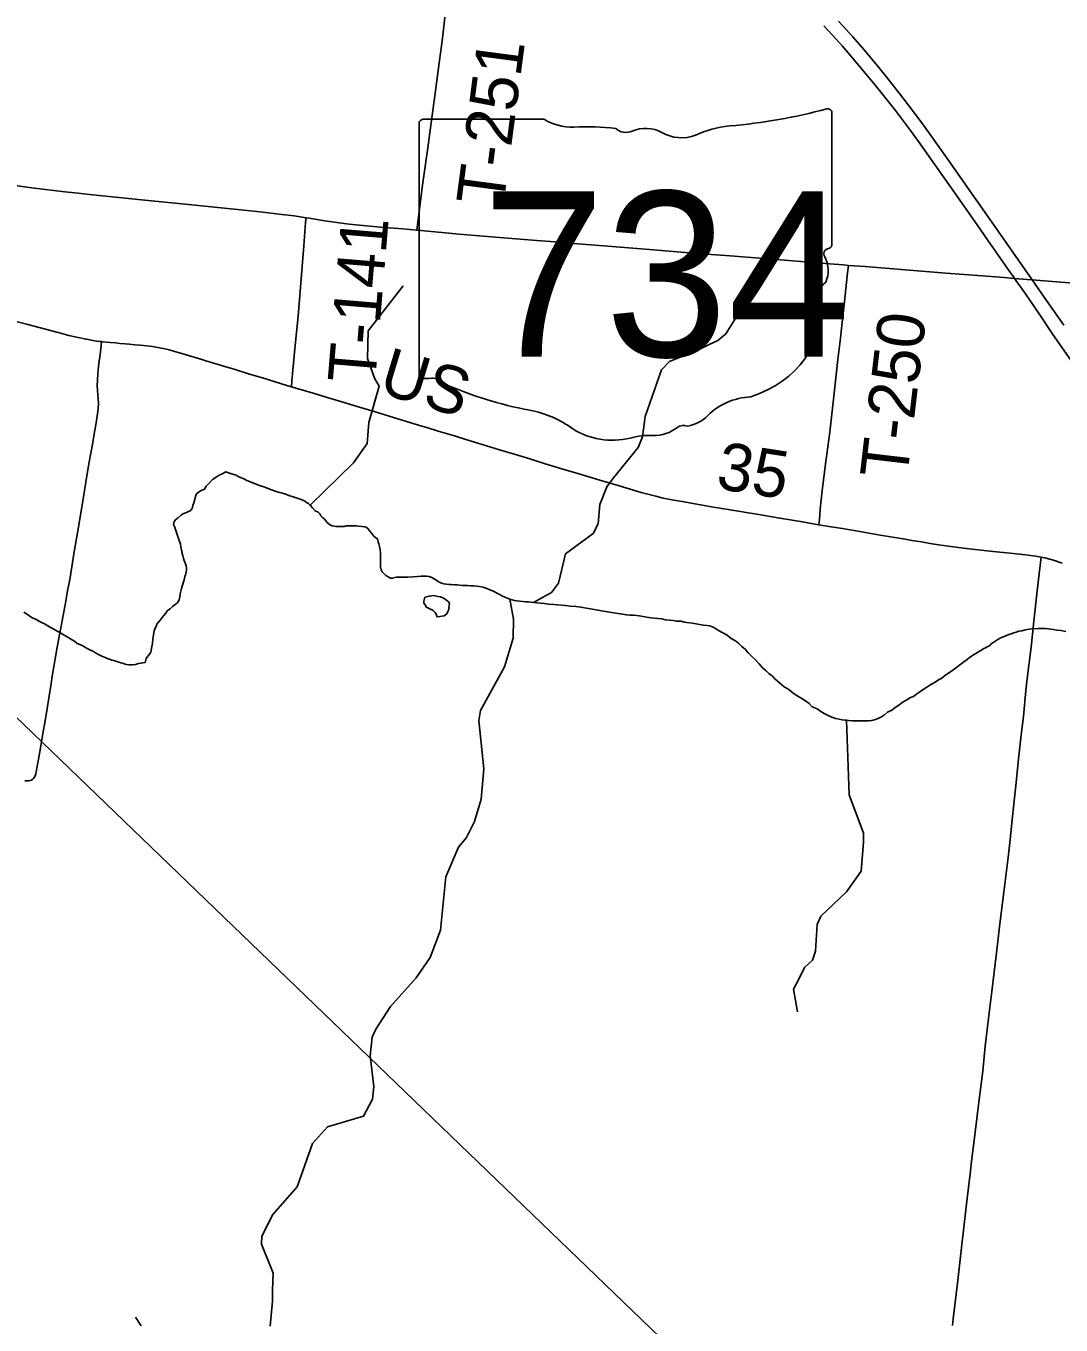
# Model space of a CAD drawing. Extents: x -49 to -8.2, y 9.4 to 23.5.
# Drawn here: x -43.786 to -43.166, y 18.097 to 18.874 of the extents above; entities that cross this region are included whole.
import ezdxf

# ---------------------------------------------------------------- set-up
doc = ezdxf.new("R2010")
doc.units = 0
for name, color, linetype in [('GM_X_County_Road', 7, 'Continuous'), ('GM_X_County_Road_Text', 7, 'Continuous'), ('GM_X_Minor_Lake', 7, 'Continuous'), ('GM_X_Minor_River', 7, 'Continuous'), ('GM_X_State_Route', 7, 'Continuous'), ('GM_X_State_Shield', 7, 'Continuous'), ('GM_X_Township_Road', 7, 'Continuous'), ('GM_X_Township_Road_Text', 7, 'Continuous'), ('GM_X_US_Route', 7, 'Continuous'), ('SC_Scratch1', 7, 'Continuous')]:
    doc.layers.add(name, color=color, linetype=linetype)

msp = doc.modelspace()

# ---------------------------------------------------------------- linework, layer by layer
at = {"layer": 'GM_X_County_Road'}
for points in [[(-43.7985, 18.69919), (-43.78469, 18.69553), (-43.76728, 18.69092), (-43.76429, 18.69012), (-43.76008, 18.68906), (-43.75554, 18.688), (-43.75341, 18.68754), (-43.74976, 18.68678), (-43.74731, 18.68634), (-43.74568, 18.68603), (-43.74346, 18.68567), (-43.74161, 18.68541), (-43.74054, 18.68529)], [(-43.74054, 18.68529), (-43.74001, 18.68523), (-43.73776, 18.68507), (-43.73529, 18.68481), (-43.7322, 18.68452), (-43.72942, 18.68426), (-43.72632, 18.68399), (-43.72385, 18.68378), (-43.72045, 18.68348), (-43.71736, 18.68319), (-43.71336, 18.68277), (-43.70998, 18.68232), (-43.70694, 18.68184), (-43.7036, 18.68118), (-43.69998, 18.68036), (-43.69729, 18.67965), (-43.6952, 18.67908), (-43.69044, 18.67768), (-43.68093, 18.67482), (-43.67797, 18.6739), (-43.66668, 18.67045), (-43.66045, 18.66855), (-43.65184, 18.6659), (-43.64411, 18.66354), (-43.6364, 18.66116), (-43.62688, 18.65828), (-43.62675, 18.65825)], [(-43.62675, 18.65825), (-43.62361, 18.65732), (-43.61914, 18.656), (-43.6117, 18.6538), (-43.60545, 18.65194), (-43.59653, 18.64927), (-43.58731, 18.64649), (-43.57721, 18.64341), (-43.56831, 18.64065), (-43.55789, 18.63754), (-43.54867, 18.63476), (-43.5457, 18.63385), (-43.53888, 18.63178), (-43.52908, 18.62885), (-43.52225, 18.6268), (-43.51246, 18.6238), (-43.5021, 18.62055), (-43.49261, 18.61768), (-43.484, 18.61505), (-43.47478, 18.61224), (-43.46079, 18.60805), (-43.45722, 18.60699), (-43.4486, 18.60439), (-43.43998, 18.60175), (-43.43106, 18.59908), (-43.41734, 18.59507), (-43.40863, 18.59274), (-43.40408, 18.59168), (-43.39768, 18.59037), (-43.39156, 18.58932), (-43.3851, 18.58816), (-43.37522, 18.58647), (-43.3578, 18.58357), (-43.35443, 18.58301), (-43.34799, 18.58196), (-43.3342, 18.57967), (-43.32073, 18.57739), (-43.3143, 18.57629), (-43.31085, 18.5757)], [(-43.31085, 18.5757), (-43.30358, 18.57446), (-43.29685, 18.57334), (-43.28766, 18.57179), (-43.27421, 18.56951), (-43.25921, 18.56695), (-43.25522, 18.56631), (-43.24939, 18.56537), (-43.24541, 18.56472), (-43.23927, 18.56374), (-43.23035, 18.56243), (-43.22264, 18.56147), (-43.20657, 18.55976), (-43.19636, 18.55873), (-43.18711, 18.55774), (-43.18098, 18.55686), (-43.17781, 18.55625)], [(-43.23096, 18.09637), (-43.23046, 18.10038), (-43.22773, 18.1232), (-43.22525, 18.14481), (-43.22442, 18.15159), (-43.22222, 18.17073), (-43.22038, 18.1871), (-43.2193, 18.19635), (-43.21859, 18.20221), (-43.21512, 18.22997), (-43.21278, 18.24853), (-43.21127, 18.26355), (-43.21002, 18.27503), (-43.2086, 18.28675), (-43.20741, 18.29631), (-43.20457, 18.31944), (-43.2025, 18.33671), (-43.20007, 18.35582), (-43.19763, 18.37649), (-43.19618, 18.38914), (-43.19533, 18.39717), (-43.19392, 18.41045), (-43.19319, 18.41756), (-43.19244, 18.42529), (-43.19135, 18.43548), (-43.1897, 18.44999), (-43.18846, 18.46079), (-43.18688, 18.47655), (-43.18608, 18.48366), (-43.18386, 18.50248), (-43.18211, 18.51791), (-43.18016, 18.53614), (-43.17897, 18.54633), (-43.17781, 18.55625)], [(-43.17781, 18.55625), (-43.17552, 18.55581), (-43.17045, 18.55447), (-43.16517, 18.55269)]]:
    msp.add_lwpolyline(points, dxfattribs=at)
at = {"layer": 'GM_X_Minor_Lake'}
msp.add_lwpolyline([(-43.54658, 18.53224), (-43.5443, 18.53297), (-43.54259, 18.53314), (-43.54145, 18.53332), (-43.53918, 18.53273), (-43.53748, 18.53252), (-43.53615, 18.53193), (-43.53521, 18.53154), (-43.5337, 18.53038), (-43.53276, 18.52961), (-43.53202, 18.52847), (-43.53242, 18.52619), (-43.53244, 18.52486), (-43.53302, 18.52373), (-43.5336, 18.5224), (-43.53532, 18.52109), (-43.53798, 18.52074), (-43.5395, 18.52057), (-43.54005, 18.5221), (-43.54061, 18.52305), (-43.54193, 18.5244), (-43.54343, 18.52517), (-43.54476, 18.52576), (-43.54589, 18.52634), (-43.54663, 18.52768), (-43.54738, 18.52864), (-43.54737, 18.52997), (-43.54677, 18.53224), (-43.54658, 18.53224)], dxfattribs=at)
at = {"layer": 'GM_X_Minor_River'}
for points in [[(-43.48174, 18.52904), (-43.47096, 18.53518), (-43.46688, 18.5408), (-43.46259, 18.55819), (-43.44607, 18.57042), (-43.44313, 18.57626), (-43.44216, 18.58782), (-43.43781, 18.59838), (-43.43392, 18.60381), (-43.4192, 18.62197), (-43.41643, 18.62837), (-43.41489, 18.6405), (-43.40511, 18.66842), (-43.40028, 18.67346), (-43.38215, 18.68073), (-43.37698, 18.68348), (-43.37144, 18.68604), (-43.36664, 18.68994), (-43.35571, 18.70759), (-43.35225, 18.7212)], [(-43.61544, 18.58735), (-43.58952, 18.61273), (-43.58135, 18.62435), (-43.58037, 18.63686), (-43.5743, 18.65859), (-43.57706, 18.66339), (-43.58121, 18.67524), (-43.58072, 18.69175), (-43.55978, 18.71872)], [(-43.73253, 18.49424), (-43.73121, 18.49385), (-43.73007, 18.49346), (-43.72894, 18.49306), (-43.72799, 18.49286), (-43.72629, 18.49227), (-43.72535, 18.49207), (-43.72421, 18.49187), (-43.72307, 18.49186), (-43.72193, 18.49185), (-43.72022, 18.49202), (-43.71832, 18.49256), (-43.7168, 18.49274), (-43.71585, 18.49292), (-43.71433, 18.49328), (-43.71374, 18.49555), (-43.71104, 18.49932), (-43.71084, 18.50065), (-43.71043, 18.50273), (-43.71003, 18.50463), (-43.70982, 18.50729), (-43.70941, 18.50975), (-43.70921, 18.51108), (-43.70901, 18.51222), (-43.70861, 18.51335), (-43.70784, 18.51486), (-43.70726, 18.51619), (-43.7063, 18.51732), (-43.70514, 18.51882), (-43.70418, 18.52014), (-43.70322, 18.52127), (-43.70206, 18.52278), (-43.70091, 18.52429), (-43.69938, 18.52541), (-43.69804, 18.52672), (-43.69632, 18.52784), (-43.69517, 18.52878), (-43.69401, 18.53067), (-43.69361, 18.53256), (-43.69341, 18.53427), (-43.69301, 18.53598), (-43.69261, 18.53749), (-43.69222, 18.53901), (-43.69182, 18.54014), (-43.69143, 18.54147), (-43.69104, 18.54279), (-43.69064, 18.54469), (-43.69025, 18.54563), (-43.69005, 18.54658), (-43.68985, 18.54753), (-43.68965, 18.54848), (-43.68964, 18.54981), (-43.68981, 18.55114), (-43.69036, 18.55285), (-43.69092, 18.55419), (-43.69147, 18.55552), (-43.69183, 18.55724), (-43.6922, 18.55819), (-43.69219, 18.55914), (-43.69256, 18.56048), (-43.69292, 18.56219), (-43.69328, 18.56428), (-43.69401, 18.56619), (-43.69677, 18.57458), (-43.69733, 18.57592), (-43.69693, 18.57762), (-43.69578, 18.57894), (-43.69463, 18.57988), (-43.69271, 18.58138), (-43.69176, 18.58213), (-43.69061, 18.58268), (-43.68928, 18.58324), (-43.68833, 18.58361), (-43.68737, 18.58398), (-43.68622, 18.58548), (-43.68582, 18.58719), (-43.68524, 18.58889), (-43.68484, 18.59022), (-43.68445, 18.59154), (-43.68425, 18.59268), (-43.68366, 18.59419), (-43.68118, 18.59607), (-43.67889, 18.59699), (-43.67773, 18.59869), (-43.67601, 18.60057), (-43.67408, 18.60282), (-43.67179, 18.60413), (-43.67007, 18.60544), (-43.66817, 18.60618), (-43.66607, 18.60729), (-43.66323, 18.60631), (-43.66134, 18.60572), (-43.65983, 18.60532), (-43.6587, 18.60455), (-43.65719, 18.60397), (-43.6553, 18.60318), (-43.65341, 18.60221), (-43.65096, 18.60123), (-43.6485, 18.60026), (-43.64586, 18.59909), (-43.64264, 18.5981)], [(-43.64264, 18.5981), (-43.63924, 18.59673), (-43.63527, 18.59536), (-43.63073, 18.59417), (-43.62828, 18.59319), (-43.62563, 18.5924), (-43.62336, 18.59162), (-43.62147, 18.59102), (-43.61996, 18.59044), (-43.61864, 18.58985), (-43.6177, 18.58908), (-43.61657, 18.58831), (-43.61544, 18.58735), (-43.61413, 18.58581), (-43.61263, 18.58409), (-43.61074, 18.58312), (-43.6098, 18.58215), (-43.60905, 18.58101), (-43.60812, 18.58005), (-43.60699, 18.57908), (-43.60624, 18.57812), (-43.60549, 18.57717), (-43.60399, 18.57582), (-43.60229, 18.57504), (-43.60001, 18.57463), (-43.59812, 18.57461), (-43.59641, 18.57459), (-43.59527, 18.57458), (-43.59394, 18.57495), (-43.5928, 18.57512), (-43.58806, 18.57507), (-43.58635, 18.57486), (-43.58465, 18.57465), (-43.58294, 18.57444), (-43.582, 18.57424), (-43.58087, 18.57328), (-43.57993, 18.57213), (-43.57862, 18.5704), (-43.57731, 18.56887), (-43.57618, 18.56791), (-43.57524, 18.56733), (-43.57488, 18.56542), (-43.57432, 18.56428), (-43.57396, 18.56256), (-43.57378, 18.56161), (-43.5736, 18.56066), (-43.57343, 18.55876), (-43.57345, 18.55705), (-43.57347, 18.55534), (-43.57349, 18.55325), (-43.57332, 18.55154), (-43.57333, 18.55021), (-43.57297, 18.54868), (-43.57241, 18.54754), (-43.57129, 18.5462), (-43.57016, 18.54523), (-43.56884, 18.54446), (-43.56733, 18.54368), (-43.56638, 18.54367), (-43.5641, 18.54422), (-43.56107, 18.54437), (-43.55708, 18.54433), (-43.55404, 18.54448), (-43.5512, 18.54464), (-43.54911, 18.54481), (-43.5474, 18.54498), (-43.54588, 18.54496), (-43.54418, 18.54475), (-43.54266, 18.54416), (-43.53965, 18.54223), (-43.53871, 18.54146), (-43.53776, 18.54107), (-43.53682, 18.54068), (-43.5355, 18.54028), (-43.53398, 18.54008), (-43.53246, 18.53987), (-43.53114, 18.53986), (-43.52905, 18.53964), (-43.52753, 18.53962), (-43.52602, 18.53942), (-43.5245, 18.5394), (-43.52279, 18.53938), (-43.52128, 18.53936), (-43.51957, 18.53916), (-43.51767, 18.53913), (-43.51578, 18.53892), (-43.51426, 18.53872), (-43.51294, 18.53851), (-43.51199, 18.53831), (-43.51086, 18.53792), (-43.50972, 18.53752), (-43.5084, 18.53694), (-43.50689, 18.53635), (-43.50576, 18.53596), (-43.50481, 18.53538), (-43.50387, 18.53499), (-43.50293, 18.53441), (-43.50199, 18.53383), (-43.50067, 18.53305), (-43.49897, 18.53227), (-43.49594, 18.5311)], [(-43.49594, 18.5311), (-43.49379, 18.51907), (-43.49399, 18.50787), (-43.49922, 18.49069), (-43.51352, 18.46455), (-43.51458, 18.4585), (-43.51149, 18.42957), (-43.51314, 18.41138), (-43.51717, 18.39797), (-43.52189, 18.38837), (-43.52673, 18.38257), (-43.53424, 18.36486), (-43.53746, 18.33302), (-43.54363, 18.31661), (-43.55199, 18.30442), (-43.56746, 18.28723), (-43.57623, 18.27372), (-43.5784, 18.26882), (-43.57954, 18.25783), (-43.5774, 18.23937), (-43.57811, 18.23179), (-43.58359, 18.22163), (-43.60512, 18.21519), (-43.6142, 18.20529), (-43.62338, 18.17925), (-43.63789, 18.16281), (-43.64456, 18.14983), (-43.64464, 18.14508), (-43.63775, 18.12768), (-43.63812, 18.11743), (-43.63805, 18.11078), (-43.63946, 18.09581)], [(-43.49594, 18.5311), (-43.49311, 18.53031), (-43.49026, 18.5299), (-43.48818, 18.52968), (-43.48647, 18.52947), (-43.48477, 18.52945), (-43.48325, 18.52925), (-43.48174, 18.52904), (-43.47984, 18.52902), (-43.47775, 18.52881), (-43.47529, 18.52859), (-43.47283, 18.52818), (-43.4696, 18.52795), (-43.46733, 18.52774), (-43.46506, 18.52752), (-43.46259, 18.52731), (-43.45956, 18.52689), (-43.45653, 18.52667), (-43.4535, 18.52625), (-43.44554, 18.52502), (-43.44327, 18.52462), (-43.43986, 18.52401), (-43.43399, 18.52299), (-43.42963, 18.52238), (-43.42604, 18.52176), (-43.42414, 18.52155), (-43.42167, 18.52153), (-43.41845, 18.52111), (-43.41505, 18.5205), (-43.41145, 18.51989), (-43.40728, 18.51965), (-43.405, 18.51944), (-43.40273, 18.51884), (-43.40027, 18.51863), (-43.39799, 18.51841), (-43.39629, 18.51801), (-43.39458, 18.51799), (-43.39344, 18.51798), (-43.39155, 18.51739), (-43.39004, 18.51718), (-43.38663, 18.51676), (-43.38341, 18.51616), (-43.38019, 18.51555), (-43.37772, 18.51533), (-43.37621, 18.51513), (-43.37526, 18.51473), (-43.37413, 18.51434), (-43.37281, 18.51357), (-43.37092, 18.51241), (-43.36847, 18.51105), (-43.36583, 18.5095), (-43.36339, 18.50757), (-43.36075, 18.50621), (-43.35887, 18.50467), (-43.35699, 18.50275), (-43.35492, 18.50102), (-43.35323, 18.4991), (-43.35117, 18.49698), (-43.34891, 18.49487), (-43.34666, 18.49238), (-43.3446, 18.49007), (-43.34253, 18.48815), (-43.34084, 18.48661), (-43.33877, 18.48507), (-43.33727, 18.48353), (-43.33163, 18.47872), (-43.32899, 18.47698), (-43.32636, 18.47486), (-43.32353, 18.47312), (-43.32108, 18.47176), (-43.31882, 18.47022), (-43.31675, 18.46867), (-43.31487, 18.46675), (-43.31185, 18.46539), (-43.30978, 18.46384), (-43.30771, 18.46268), (-43.30544, 18.46151), (-43.30318, 18.46054), (-43.30091, 18.45975), (-43.29882, 18.45935), (-43.29693, 18.45895), (-43.29542, 18.45874), (-43.29428, 18.45873), (-43.29314, 18.45853), (-43.29106, 18.45831), (-43.28954, 18.4583), (-43.28802, 18.45828), (-43.28575, 18.45825), (-43.28328, 18.45823), (-43.28119, 18.45839), (-43.2791, 18.45856), (-43.27701, 18.4591), (-43.27491, 18.45984), (-43.27339, 18.46077), (-43.27167, 18.46189), (-43.26975, 18.46358), (-43.26727, 18.46469), (-43.26517, 18.46619), (-43.26307, 18.46769), (-43.26097, 18.46918), (-43.25829, 18.47086)], [(-43.78705, 18.52335), (-43.78479, 18.522), (-43.78253, 18.52045), (-43.77913, 18.51871), (-43.77687, 18.51735), (-43.7746, 18.51638), (-43.77253, 18.51521), (-43.77027, 18.51386), (-43.76763, 18.51231), (-43.76008, 18.50804), (-43.75839, 18.50707), (-43.75669, 18.50591), (-43.755, 18.50457), (-43.75254, 18.50359), (-43.75066, 18.50262), (-43.74915, 18.50165), (-43.74783, 18.50107), (-43.74669, 18.50048), (-43.74537, 18.49971), (-43.74405, 18.49893), (-43.74273, 18.49816), (-43.74141, 18.49757), (-43.74028, 18.49699), (-43.73839, 18.49621), (-43.73745, 18.49582), (-43.73594, 18.49523), (-43.73405, 18.49464), (-43.73253, 18.49424)], [(-43.25829, 18.47086), (-43.256, 18.47217), (-43.25429, 18.47291), (-43.25295, 18.47384), (-43.25123, 18.47515), (-43.24912, 18.47665), (-43.24683, 18.47795), (-43.24378, 18.48001), (-43.24129, 18.4815), (-43.23919, 18.48281), (-43.23728, 18.48393), (-43.23575, 18.48524), (-43.23422, 18.48617), (-43.23269, 18.48729), (-43.23078, 18.4886), (-43.22581, 18.49216), (-43.22409, 18.49366), (-43.22218, 18.49496), (-43.22065, 18.49628), (-43.21912, 18.49721), (-43.21778, 18.49814), (-43.21644, 18.49889), (-43.21511, 18.49982), (-43.21358, 18.50057), (-43.21243, 18.50131), (-43.2111, 18.50206), (-43.21014, 18.50262), (-43.20862, 18.50336), (-43.20766, 18.5043), (-43.2067, 18.50505), (-43.20556, 18.5058), (-43.20441, 18.50654), (-43.20307, 18.50729), (-43.20155, 18.50822), (-43.20002, 18.50877), (-43.1985, 18.50933), (-43.19717, 18.50988), (-43.19583, 18.51044), (-43.19412, 18.51099), (-43.19279, 18.51135), (-43.19107, 18.5119), (-43.18936, 18.51226), (-43.18727, 18.51281), (-43.18499, 18.51316), (-43.18252, 18.51333), (-43.17986, 18.51349), (-43.17739, 18.51365), (-43.17531, 18.51362), (-43.17341, 18.51341), (-43.17057, 18.513), (-43.16849, 18.5126), (-43.16602, 18.51238), (-43.16299, 18.51178)], [(-43.29428, 18.45873), (-43.29272, 18.414), (-43.28423, 18.39106), (-43.28413, 18.38574), (-43.28558, 18.3683), (-43.29432, 18.35593), (-43.30974, 18.3414), (-43.31192, 18.33631), (-43.31296, 18.32038), (-43.31476, 18.31509), (-43.31957, 18.31062), (-43.32253, 18.30441), (-43.32606, 18.29764), (-43.32365, 18.28411)], [(-43.71676, 18.09608), (-43.72008, 18.10127)]]:
    msp.add_lwpolyline(points, dxfattribs=at)
at = {"layer": 'GM_X_State_Route'}
for points in [[(-43.79232, 18.77868), (-43.78214, 18.77747), (-43.76241, 18.77507), (-43.75438, 18.77422), (-43.74759, 18.77348), (-43.71452, 18.77008), (-43.6864, 18.76717), (-43.66877, 18.76535), (-43.6455, 18.76298), (-43.6325, 18.76146), (-43.6251, 18.76053), (-43.61802, 18.75949), (-43.61617, 18.75922), (-43.60666, 18.75768), (-43.59808, 18.75634), (-43.59223, 18.75566), (-43.57338, 18.75381), (-43.56007, 18.75274), (-43.55173, 18.75203), (-43.54923, 18.75182), (-43.52633, 18.74973), (-43.51178, 18.74852), (-43.49228, 18.74681), (-43.48238, 18.74597), (-43.46906, 18.745), (-43.45759, 18.74414), (-43.4322, 18.74206), (-43.40992, 18.74018), (-43.3839, 18.73816), (-43.36408, 18.73659), (-43.34394, 18.73503), (-43.30462, 18.73183), (-43.29616, 18.73119)], [(-43.29616, 18.73119), (-43.29317, 18.73096), (-43.28325, 18.73021), (-43.23495, 18.72632), (-43.21295, 18.72466), (-43.19997, 18.72363)], [(-43.19997, 18.72363), (-43.19369, 18.72313), (-43.18631, 18.72254), (-43.18312, 18.72229), (-43.16619, 18.72093), (-43.14977, 18.71971), (-43.10642, 18.71632), (-43.05496, 18.71206)]]:
    msp.add_lwpolyline(points, dxfattribs=at)
at = {"layer": 'GM_X_State_Shield'}
for p, q in [((-43.30309, 18.74366), (-43.30309, 18.82217)), ((-43.55028, 18.81587), (-43.55028, 18.66578)), ((-43.47545, 18.81845), (-43.54785, 18.81845)), ((-43.30312, 18.74368), (-43.30309, 18.74366))]:
    msp.add_line(p, q, dxfattribs=at)
for centre, major_axis, start_param, end_param in [((-43.39114, 19.02308), (0.26214, 0), 4.814394, 5.042369), ((-43.30583, 18.8225), (0.00275, 0), 6.141152, 7.989035), ((-43.54745, 18.81619), (0.00286, 0), 1.712693, 3.28349), ((-43.45822, 18.83588), (0.02778, 0), 4.042523, 4.731795), ((-43.44901, 18.73419), (0.09971, 0), 1.404758, 1.657858), ((-43.42637, 18.81697), (0.00801, 0), 3.836095, 5.185415), ((-43.4146, 18.79962), (0.01666, 0), 0.950623, 2.079405), ((-43.35771, 18.77261), (0.05274, 0), 1.699011, 2.107814), ((-43.3931, 18.82341), (0.02004, 0), 4.081561, 5.145723), ((-43.30603, 18.74335), (0.00294, 0), 5.05454, 6.418171), ((-43.30373, 18.73789), (0.00426, 0), 1.883978, 3.671073), ((-43.33082, 18.72797), (0.02556, 0), 5.934695, 6.695948), ((-43.29323, 18.7108), (0.0186, 0), 2.387724, 3.262537), ((-43.37646, 18.70081), (0.06557, 0), 5.101752, 6.440018), ((-43.54742, 18.66545), (0.00289, 0), 3.00124, 4.508301), ((-43.54698, 18.68081), (0.02205, 0), 4.665946, 4.897461), ((-43.54247, 18.65712), (0.00795, 0), 0.519207, 1.627899), ((-43.4421, 18.79197), (0.1893, 0), 4.195997, 4.488961), ((-43.34881, 18.62364), (0.03591, 0), 1.647645, 2.488434), ((-43.49854, 18.59835), (0.05923, 0), 0.823519, 1.323587), ((-43.41002, 18.64514), (0.02002, 0), 4.691044, 5.507374), ((-43.39191, 18.6306), (0.00564, 0), 1.147584, 2.315152), ((-43.39431, 18.65123), (0.02118, 0), 4.937069, 5.64225), ((-43.43448, 18.65637), (0.03758, 0), 4.026481, 4.996735), ((-43.41277, 18.60448), (0.03088, 0), 1.495662, 1.94098)]:
    msp.add_ellipse(centre, major_axis=major_axis, ratio=0.8, start_param=start_param, end_param=end_param, dxfattribs=at)
at = {"layer": 'GM_X_Township_Road'}
for points in [[(-43.55173, 18.75203), (-43.55127, 18.7554), (-43.55023, 18.7631), (-43.54843, 18.77759), (-43.54632, 18.79299), (-43.54517, 18.8013), (-43.54311, 18.81639), (-43.54096, 18.83241), (-43.5392, 18.84471), (-43.53636, 18.86691), (-43.53494, 18.87926), (-43.53406, 18.88886), (-43.53344, 18.89691), (-43.53195, 18.91519), (-43.52992, 18.93997), (-43.52914, 18.9507)], [(-43.62675, 18.65825), (-43.62643, 18.6619), (-43.62475, 18.68094), (-43.62271, 18.7006), (-43.6193, 18.74262), (-43.61825, 18.75654), (-43.61802, 18.75949)], [(-43.29805, 18.6873), (-43.29758, 18.69134), (-43.29546, 18.7111), (-43.29368, 18.72652), (-43.29317, 18.73096)], [(-43.76249, 18.52666), (-43.76212, 18.52864), (-43.76096, 18.53505), (-43.7595, 18.54297), (-43.75658, 18.56073), (-43.75491, 18.57084), (-43.75214, 18.58734), (-43.74989, 18.60112), (-43.74779, 18.61337), (-43.74594, 18.62377), (-43.74483, 18.6302), (-43.74397, 18.6354), (-43.74295, 18.64214), (-43.74252, 18.64528), (-43.74235, 18.64847), (-43.74254, 18.65113), (-43.74287, 18.65577), (-43.74302, 18.65918), (-43.74294, 18.66229), (-43.7426, 18.66631), (-43.74199, 18.67217), (-43.74131, 18.6777), (-43.74097, 18.68109), (-43.74054, 18.68529)], [(-43.31085, 18.5757), (-43.31059, 18.57879), (-43.31009, 18.58498), (-43.30897, 18.5961), (-43.30669, 18.61364), (-43.30444, 18.6312), (-43.30143, 18.65804), (-43.2995, 18.67469), (-43.29805, 18.6873)], [(-43.78647, 18.42243), (-43.78524, 18.42229), (-43.78429, 18.42233), (-43.78324, 18.42252), (-43.78255, 18.4228), (-43.78189, 18.42318), (-43.78126, 18.42372), (-43.78075, 18.42441), (-43.78022, 18.42539), (-43.77981, 18.42649), (-43.77955, 18.42772), (-43.77788, 18.43753), (-43.77636, 18.44575), (-43.77554, 18.45064), (-43.7743, 18.45829), (-43.7729, 18.46687), (-43.7707, 18.48067), (-43.77006, 18.48496), (-43.76873, 18.49292), (-43.76831, 18.49537), (-43.76705, 18.50239), (-43.76569, 18.50971), (-43.7635, 18.52131), (-43.76249, 18.52666)]]:
    msp.add_lwpolyline(points, dxfattribs=at)
at = {"layer": 'GM_X_US_Route'}
for points in [[(-43.29914, 18.87712), (-43.29058, 18.8677), (-43.28402, 18.86024), (-43.27581, 18.85051), (-43.26914, 18.84233), (-43.26055, 18.83131), (-43.25045, 18.81793), (-43.24424, 18.80939), (-43.23201, 18.79217), (-43.22188, 18.77764), (-43.20639, 18.75549), (-43.18312, 18.72229), (-43.17733, 18.71402), (-43.16414, 18.69519)], [(-43.30793, 18.87441), (-43.30034, 18.86618), (-43.29703, 18.86247), (-43.29333, 18.85827), (-43.28813, 18.85209), (-43.27783, 18.83963), (-43.27295, 18.83358), (-43.26505, 18.82359), (-43.25604, 18.81169), (-43.2513, 18.80515), (-43.24263, 18.79301), (-43.23208, 18.77802), (-43.21481, 18.75333), (-43.21126, 18.74823), (-43.19932, 18.73118), (-43.19506, 18.72507), (-43.19501, 18.725)], [(-43.19501, 18.725), (-43.19369, 18.72313), (-43.18717, 18.71392), (-43.1789, 18.70187), (-43.17112, 18.69026), (-43.1596, 18.67369)]]:
    msp.add_lwpolyline(points, dxfattribs=at)
at = {"layer": 'SC_Scratch1'}
msp.add_line((-49.03536, 23.5097), (-36.43741, 11.37924), dxfattribs=at)

# ---------------------------------------------------------------- texts
at = {"layer": 'GM_X_County_Road_Text'}
for s, rotation, p in [('US', 343.09594, (-43.57554, 18.65504)), ('35', 351.20247, (-43.37318, 18.59745))]:
    msp.add_text(s, height=0.028409, rotation=rotation, dxfattribs=at).set_placement(p)
at = {"layer": 'GM_X_State_Shield'}
msp.add_text('734', height=0.098877, dxfattribs=at).set_placement((-43.51253, 18.67636))
at = {"layer": 'GM_X_Township_Road_Text'}
for s, rotation, p in [('T-251', 82.46049, (-43.49991, 18.7658)), ('T-141', 85.23952, (-43.57675, 18.65977)), ('T-250', 83.29784, (-43.25815, 18.6024))]:
    msp.add_text(s, height=0.028409, rotation=rotation, dxfattribs=at).set_placement(p)

doc.saveas('drawing.dxf')
